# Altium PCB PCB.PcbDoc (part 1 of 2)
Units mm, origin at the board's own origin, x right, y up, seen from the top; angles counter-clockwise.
Board outline 73.15 x 70.89 mm, 4 copper layers (Top Layer, Int1 (GND), Int2 (PWR), Bottom Layer), stack 1.369 mm thick; 101 components, 61 nets, 289 pads, 185 vias.
Unrouted connection lines stored in the file: 20.
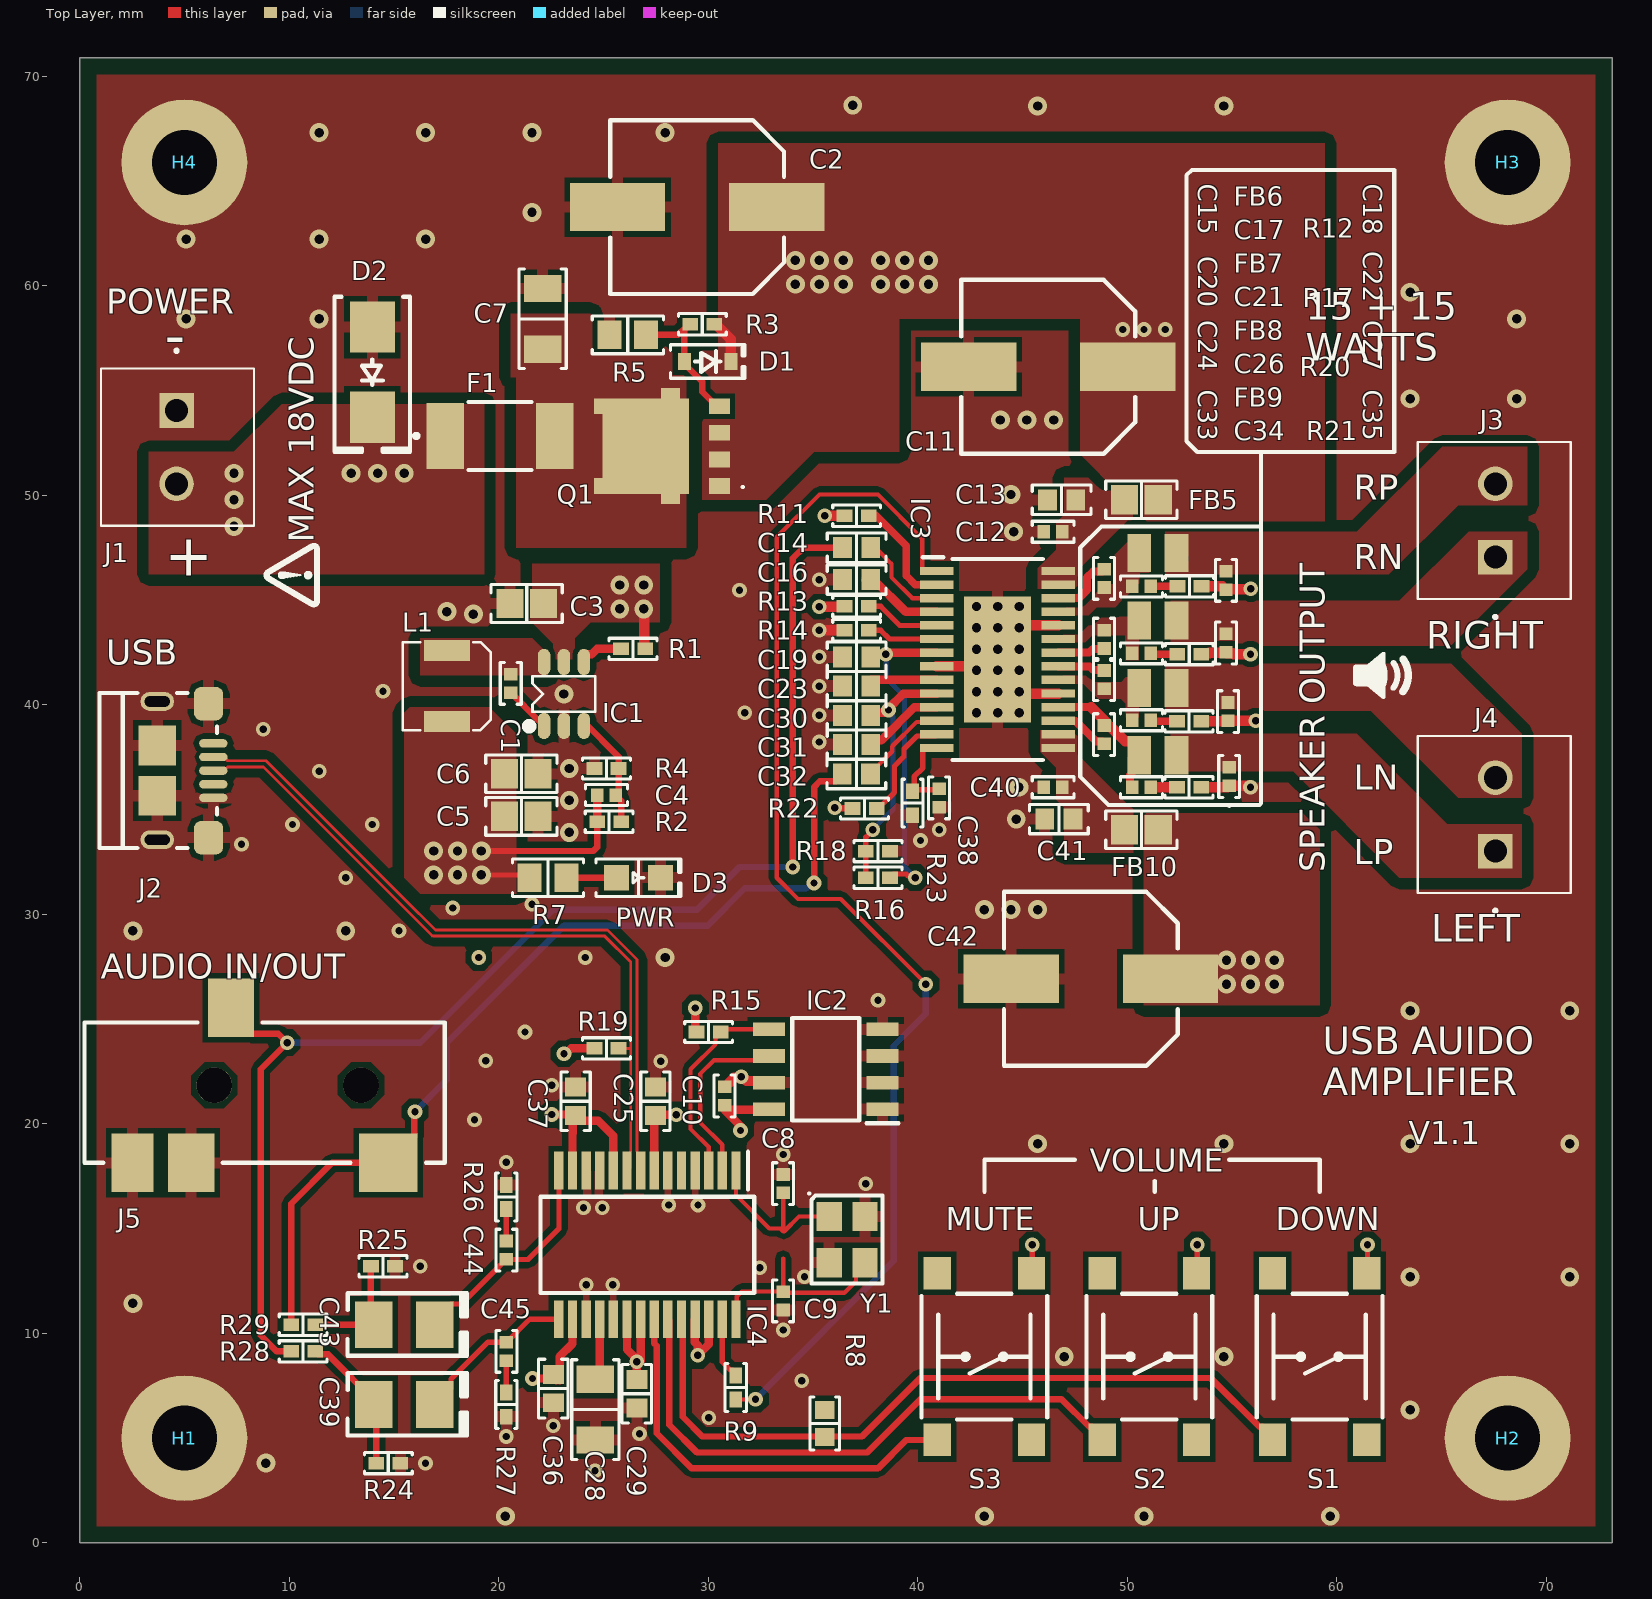
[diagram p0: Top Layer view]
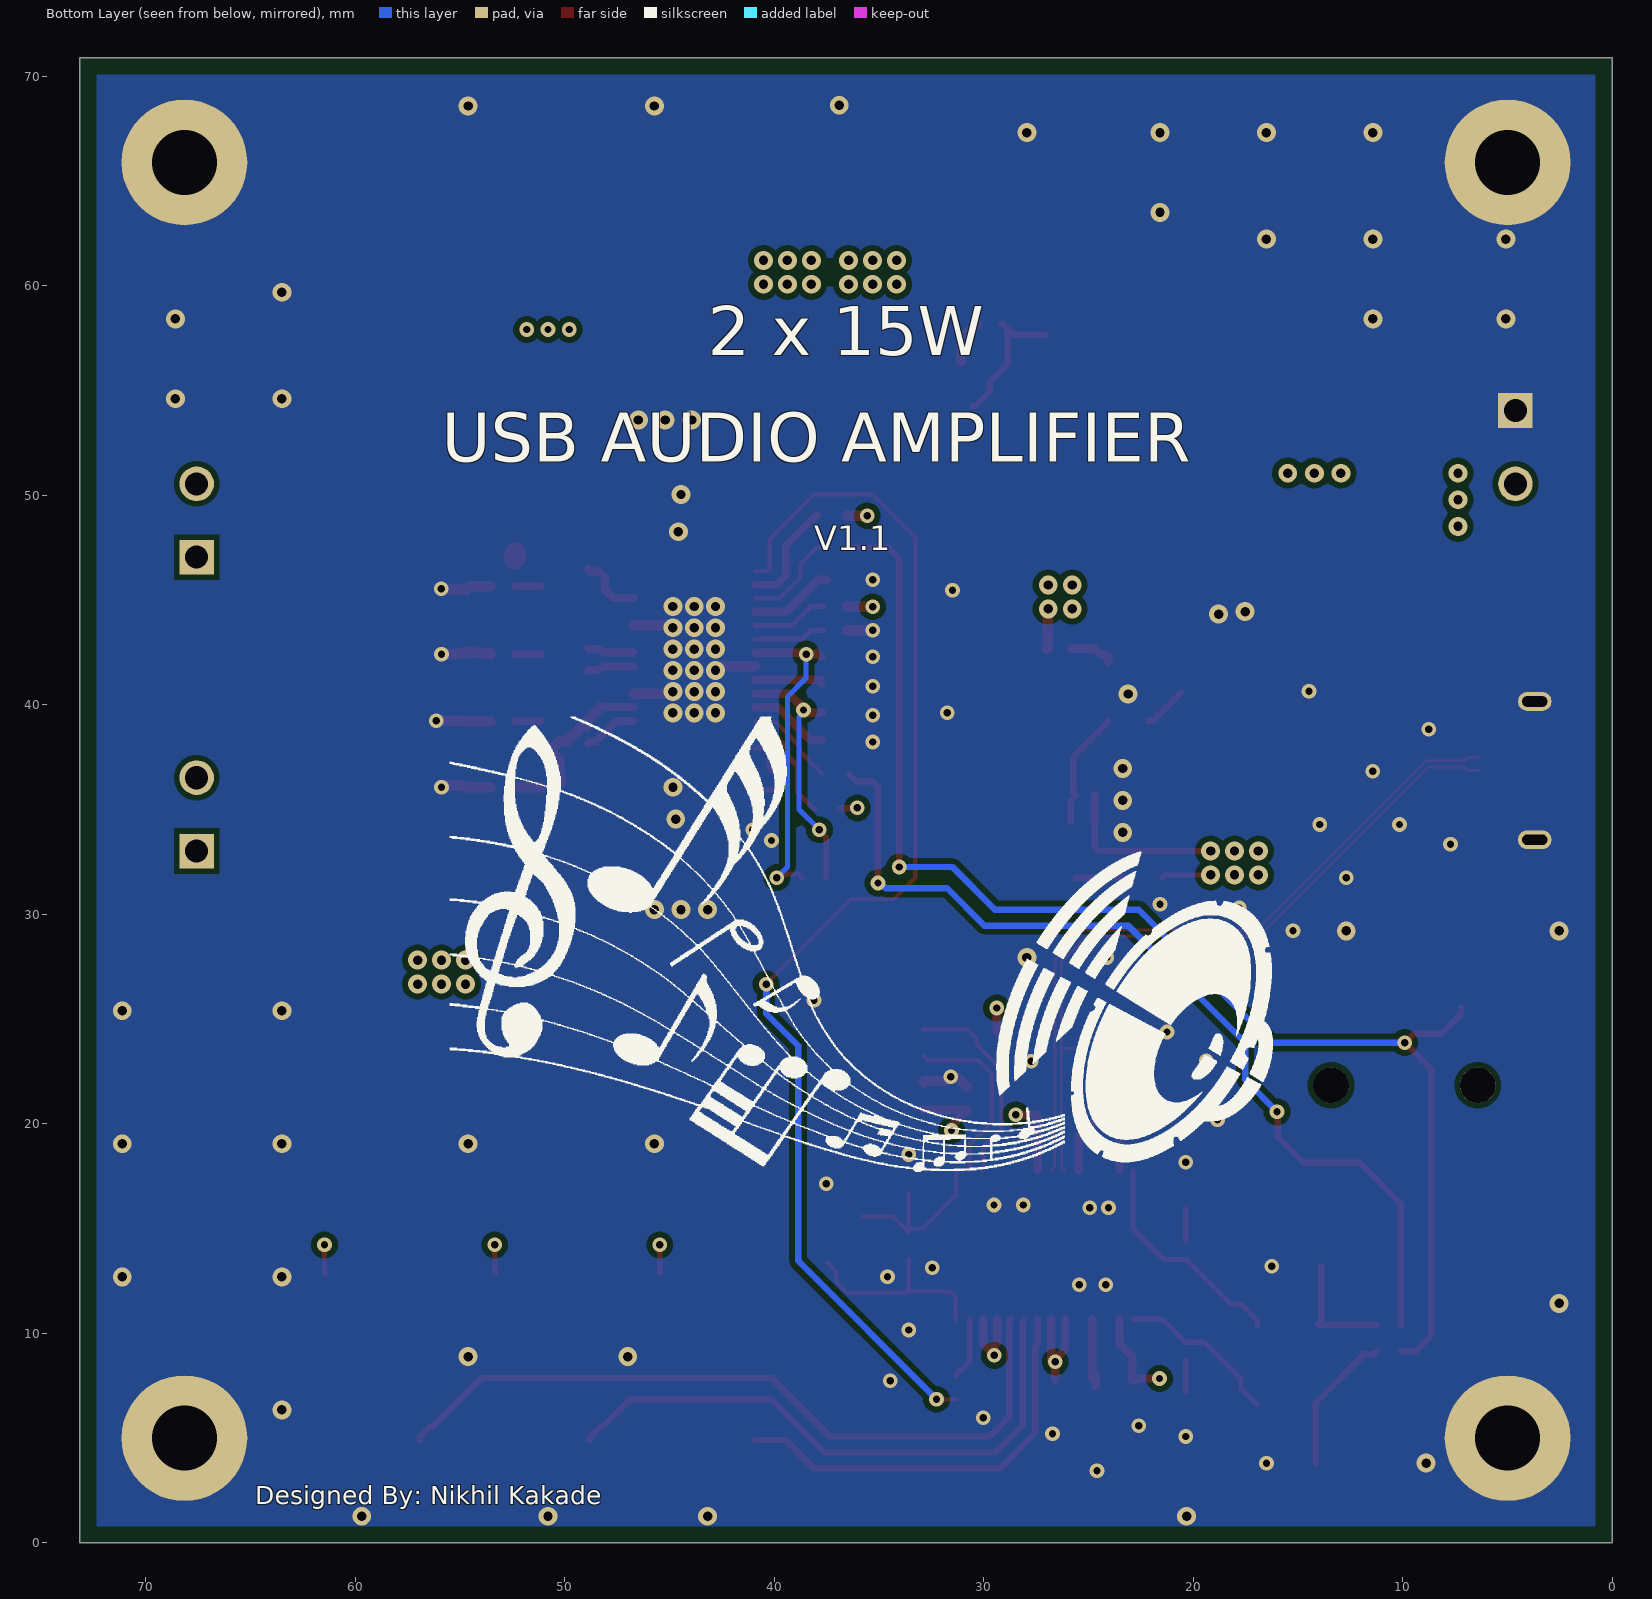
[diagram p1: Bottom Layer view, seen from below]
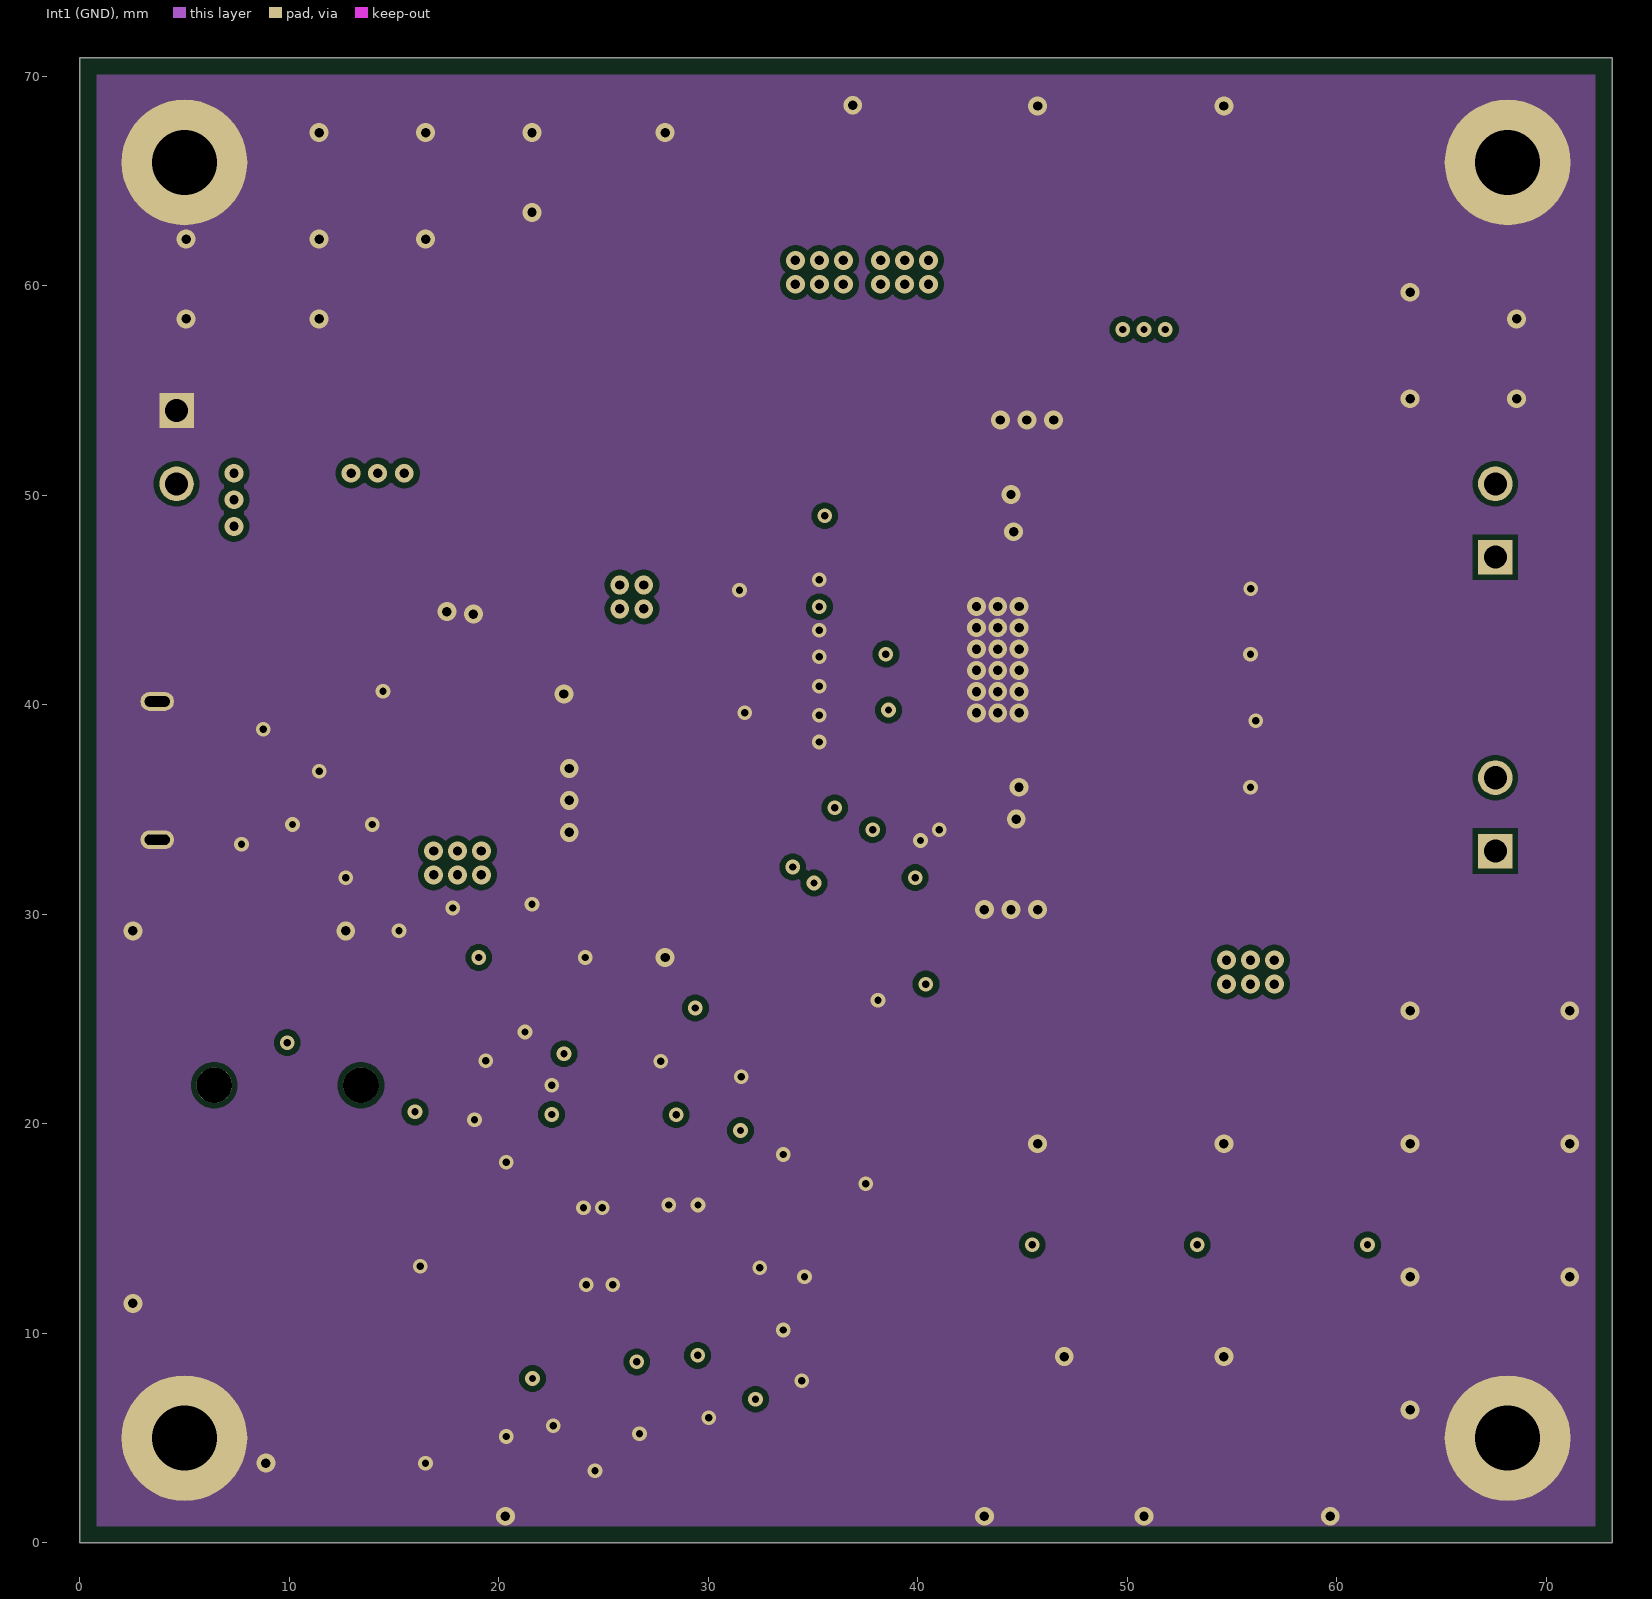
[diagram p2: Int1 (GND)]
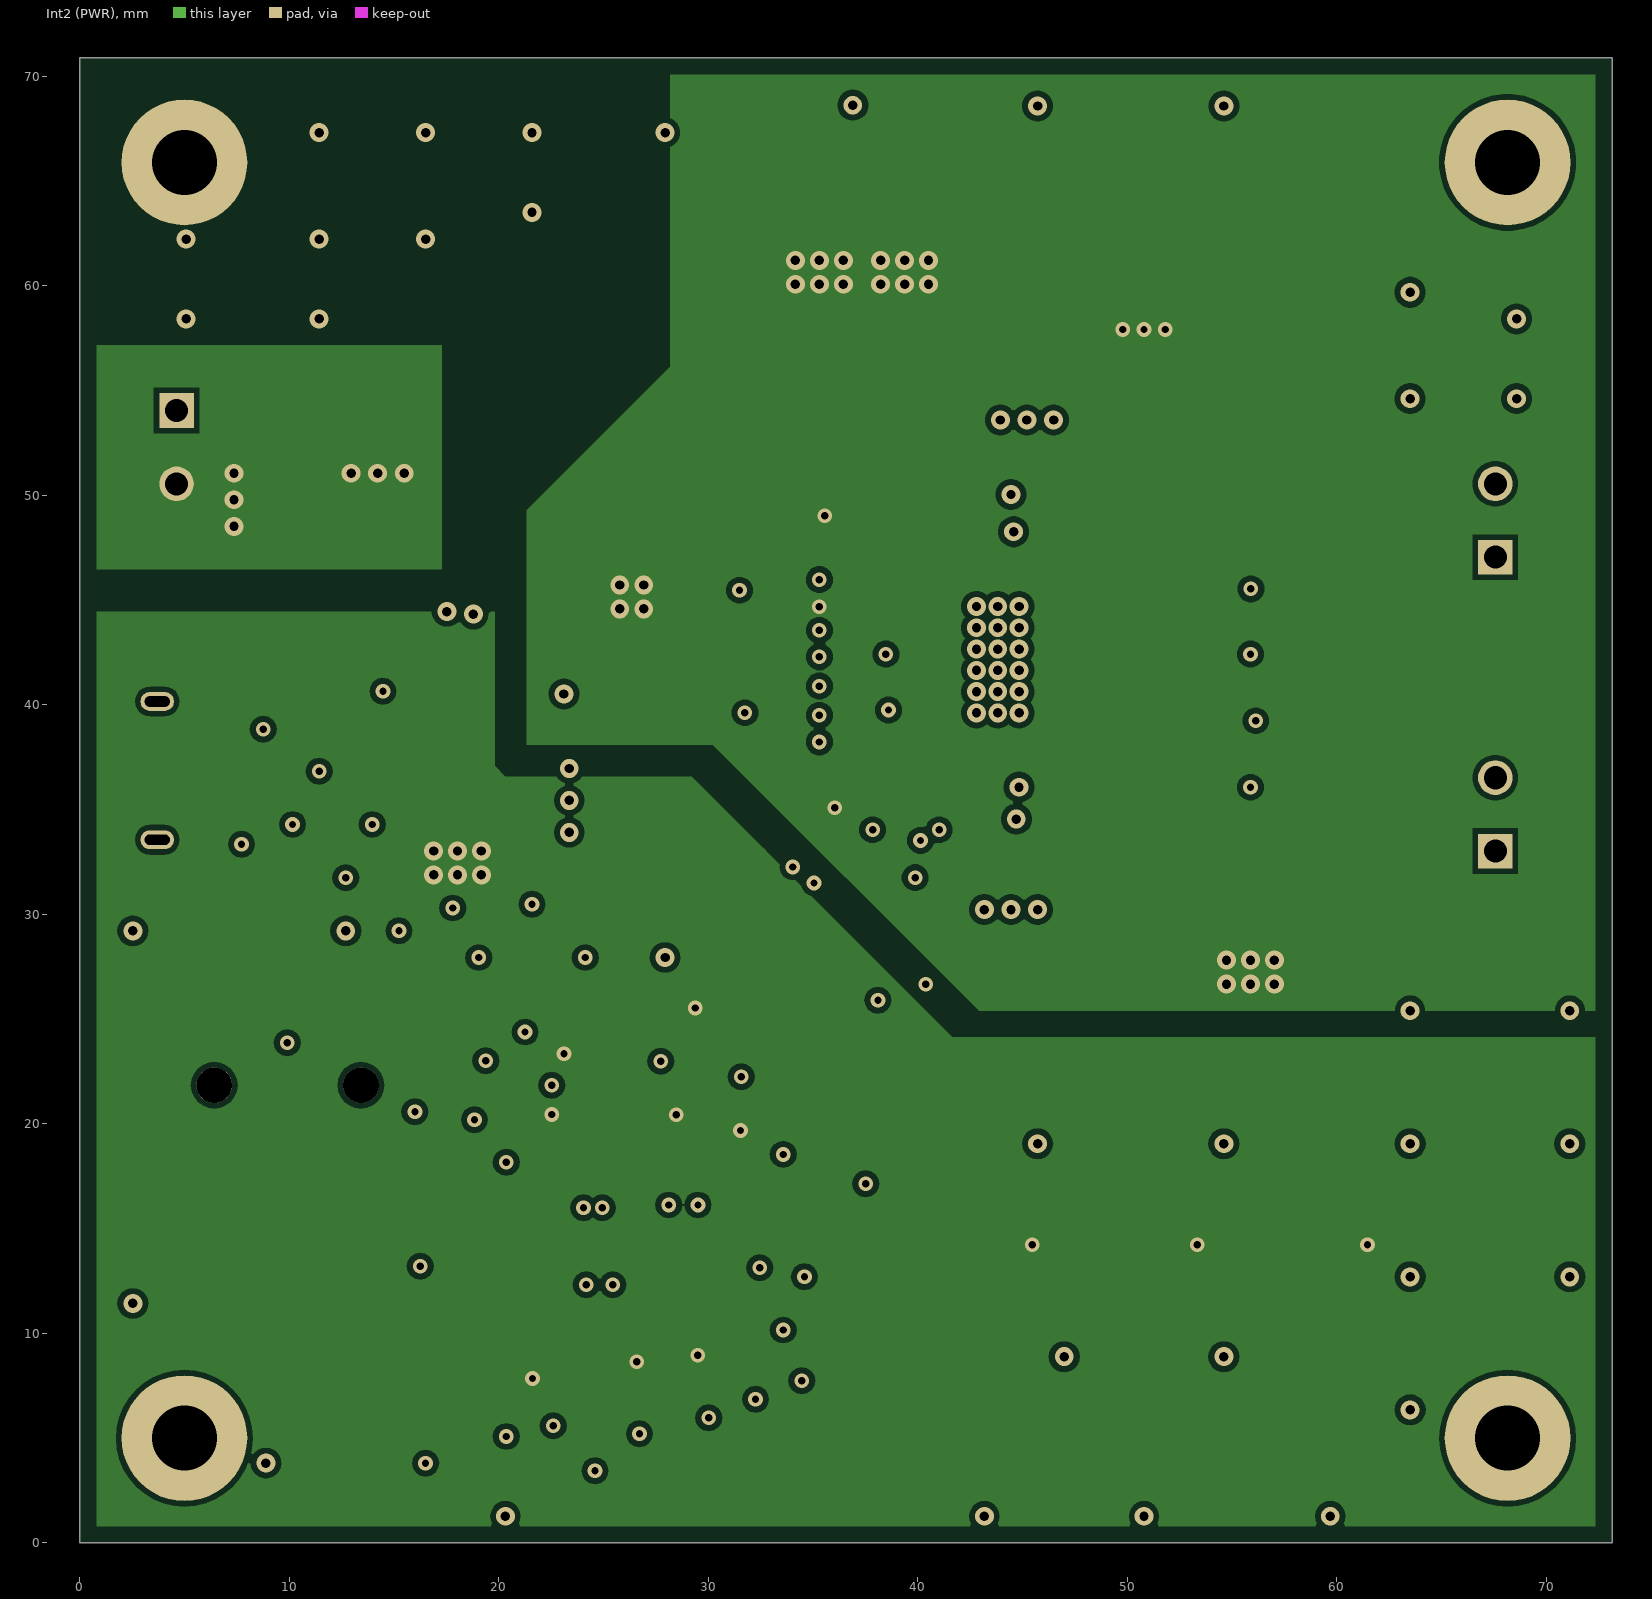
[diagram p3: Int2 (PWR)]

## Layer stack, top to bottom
Top Solder: solder mask 0.0254, SM-001, Dk 4
Top Layer: signal copper 0.035
Dielectric 1: prepreg 0.1295, PP-017, Dk 4.3
Dielectric 2: prepreg 0.1295, PP-017, Dk 4.3
Int1 (GND): signal copper 0.035
Dielectric 3: core 0.7112, Core-039, Dk 4.8
Int2 (PWR): signal copper 0.035
Dielectric 4: prepreg 0.1295, PP-017, Dk 4.3
Dielectric 5: prepreg 0.1295, PP-017, Dk 4.3
Bottom Layer: signal copper 0.035
Bottom Solder: solder mask 0.0254, SM-001, Dk 4

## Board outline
0,0 73.152,0 73.152,70.888 0,70.888

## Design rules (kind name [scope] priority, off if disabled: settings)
AssemblyTestpoint [All] p1: testpointundercomponent=TRUE minsize=1.016 maxsize=2.54 preferedsize=1.524 minholesize=0 maxholesize=1.016 preferedholesize=0.813 testpointgrid=0.025 usegrid=TRUE gridoriginx=-22.86 gridoriginy=-3.429 gridtolerance=0 allowsidetop=TRUE allowsidebottom=TRUE
BoardOutlineClearance [All] p1: gap=0.8 ignorepadtopadclearanceinfootprint=FALSE except(0.4: Text-OutlineEdge)
Clearance "DIFF PAIR TO PAIR_VIA" [InDifferentialPairClass('SS_DIFF85') AND IsVia OR InDifferentialPairClass('HS_DIFF90') AND Isvia vs InDifferentialPairClass('SS_DIFF85') AND IsVia OR InDifferentialPairClass('HS_DIFF90') AND IsVia] p1: gap=0.254 ignorepadtopadclearanceinfootprint=TRUE
Clearance "SuperSpeed Clearance" [InNetClass('SS_DIFF85') OR InNetClass('HS_DIFF90') vs InNet('GND') OR InNet('+1V2') OR InNet('+3V3') OR InNet('+5V') OR InNet('+1V05')] p2: gap=0.178 ignorepadtopadclearanceinfootprint=TRUE except(0.127: Arc-SMDPad Track-SMDPad; 0.152: Arc-Arc Arc-Track Arc-Via Track-Track Track-Via SMDPad-Via; 0.381: Arc-Fill Arc-Poly Arc-Region Track-Fill Track-Poly Track-Region Via-Fill Via-Poly Via-Region; 0.4: Fill-Fill Fill-Poly Fill-Region Poly-Poly Poly-Region Region-Region)
Clearance "Pair to Pair SS Clearance" [InNetClass('SS_DIFF85') vs InAnyNet and IsDifferentialPair] p3: gap=0.5 ignorepadtopadclearanceinfootprint=TRUE
Clearance "Clearance_PWR _plane" [InNamedPolygon('NONET_L03_P031')  OR InNamedPolygon('+1V05_L04_P023')] p4: gap=0.203 ignorepadtopadclearanceinfootprint=TRUE except(0.5: Fill-Fill Fill-Poly Fill-Region Poly-Poly Poly-Region Region-Region)
Clearance [All] p5: gap=0.254 ignorepadtopadclearanceinfootprint=TRUE except(0: Arc-Hole Track-Hole SMDPad-Hole THPad-Hole Via-Hole Fill-Hole Poly-Hole Region-Hole Text-Hole; 0.102: Arc-SMDPad Arc-Via Track-SMDPad Track-Via; 0.127: Arc-Arc Arc-Track Arc-THPad Track-Track Track-THPad SMDPad-SMDPad SMDPad-THPad SMDPad-Via Via-Via; 0.279: Via-Fill Via-Poly Via-Region; 0.5: Fill-Fill Fill-Poly Fill-Region Poly-Poly Poly-Region Region-Region)
DiffPairsRouting "SuperSpeed DiffPairs_85" [InDifferentialPairClass('SS_DIFF85')] p1: maxlimit=0.152 minlimit=0.152 mostfreqgap=0.152 toplayer_minwidth=0.159 toplayer_maxwidth=0.159 toplayer_prefwidth=0.159 midlayer1_minwidth=0.159 midlayer1_maxwidth=0.159 midlayer1_prefwidth=0.159 midlayer2_minwidth=0.159 midlayer2_maxwidth=0.159 midlayer2_prefwidth=0.159 bottomlayer_minwidth=0.159 bottomlayer_maxwidth=0.159 bottomlayer_prefwidth=0.159 maxuncoupledlength=12.7
DiffPairsRouting "HighSpeed DiffPairs_90" [InDifferentialPairClass('HS_DIFF90')] p2: maxlimit=0.152 minlimit=0.152 mostfreqgap=0.152 toplayer_minwidth=0.141 toplayer_maxwidth=0.141 toplayer_prefwidth=0.141 midlayer1_minwidth=0.141 midlayer1_maxwidth=0.141 midlayer1_prefwidth=0.141 midlayer2_minwidth=0.141 midlayer2_maxwidth=0.141 midlayer2_prefwidth=0.141 bottomlayer_minwidth=0.141 bottomlayer_maxwidth=0.141 bottomlayer_prefwidth=0.141 maxuncoupledlength=12.7
FabricationTestpoint [All] p1: side=3 testpointundercomponent=TRUE minsize=1.016 maxsize=2.54 preferedsize=1.524 minholesize=0 maxholesize=1.016 preferedholesize=0.813 testpointgrid=0.025 allowsidetop=TRUE allowsidebottom=TRUE usegrid=TRUE gridoriginx=-22.86 gridoriginy=-3.429 gridtolerance=0
HoleSize [All] p1: absolutevalues=TRUE maxlimit=6 minlimit=0.2 maxpercent=80.000 minpercent=20.000
MatchedLengths "DIFF90 HS" [InDifferentialPairClass('HS_DIFF90')] p1: tolerance=0.203 checknetsindiffpair=TRUE checkdiffpairvsdiffpair=FALSE checkxsignals=FALSE checkothers=FALSE
MatchedLengths "DIFF85 SS" [InDifferentialPairClass('SS_DIFF85')] p2: tolerance=0.051 checknetsindiffpair=TRUE checkdiffpairvsdiffpair=FALSE checkxsignals=FALSE checkothers=FALSE
MinimumSolderMaskSliver [All] p1: minsoldermaskwidth=0.09
PlaneClearance [All] p1: clearance=0.762
PolygonConnect PolygonConnect_1 [All vs IsNamedPolygon('GND_L01_P080')] p1: thpad.connectstyle=Direct thpad.reliefconductorwidth=0.254 thpad.reliefentries=4 thpad.polygonreliefangle="90 Angle" thpad.airgapwidth=0.254 smdpad.connectstyle=Relief smdpad.reliefconductorwidth=0.55 smdpad.reliefentries=4 smdpad.polygonreliefangle="90 Angle" smdpad.airgapwidth=0.254 via.connectstyle=Direct via.reliefconductorwidth=0.254 via.reliefentries=4 via.polygonreliefangle="90 Angle" via.airgapwidth=0.254
PolygonConnect [All] p2: connectstyle=Direct reliefconductorwidth=0.254 reliefentries=4 polygonreliefangle="90 Angle" airgapwidth=0.254
RoomDefinition Power [InComponentClass('Power')] p1: confinementstyle=ConfineIn formatcopy=TRUE lockcomponents=FALSE outline 0,-7.112 9.144,-7.112 9.144,2.642 0,2.642
RoomDefinition Audio [InComponentClass('Audio')] p2: confinementstyle=ConfineIn formatcopy=TRUE lockcomponents=FALSE outline 178.943,155.067
RoutingCorners Differential_Corners [(InDifferentialPairClass('HS_DIFF90'))] p1: cornerstyle=Round minsetback=5 maxsetback=5
RoutingCorners [All] p2: cornerstyle=45-Degree minsetback=2.54 maxsetback=2.54
RoutingVias "Diff Pair Via" [InDifferentialPairClass('All Differential Pairs')] p1: holewidth=0.203 width=0.406 viastyle="Through Hole" minholewidth=0.203 minwidth=0.406 maxholewidth=0.203 maxwidth=0.406
RoutingVias [All] p2: holewidth=0.35 width=0.7 viastyle="Through Hole" minholewidth=0.2 minwidth=0.35 maxholewidth=0.711 maxwidth=1.27
SolderMaskExpansion [All] p1: expansion=0.102 istentingtop=FALSE
Width [All] p1: maxlimit=3 minlimit=0.102 preferedwidth=0.127
23 further rules are at their usual default settings.

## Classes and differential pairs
differential pair class HS_DIFF90: AUD_D D1 D2 D3 DAC_D DOWN_D1 DOWN_D2 HSD3 HUB_D UP_D
net class HS_DIFF90: AUD_D_N AUD_D_P DB_N DB_P
component class Power: C1 C2 C3 C4 C5 C6 C7 D1 D2 D3 F1 H1 H2 H3 H4 IC1 J1 J2 L1 Q1 R1 R2 R3 R4 R5 R7
component class Audio: C8 C9 C10 C11 C12 C13 C14 C15 C16 C17 C18 C19 C20 C21 C22 C23 C24 C25 C26 C27 C28 C29 C30 C31 C32 C33 C34 C35 C36 C37 C38 C39 C40 C41 C42 C43 C44 C45 FB5 FB6 FB7 FB8 FB9 FB10 IC2 IC3 IC4 J3 J4 J5 R8 R9 R11 R12 R13 R14 R15 R16 R17 R18 R19 R20 R21 R22 R23 R24 R25 R26 R27 R28 R29 S1 S2 S3 Y1
differential pair AUD_D: +AUD_D_P -AUD_D_N

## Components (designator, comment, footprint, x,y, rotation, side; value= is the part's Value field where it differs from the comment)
C1 "0.1µF" "CAP 0402_1005" 20.574,41.025 r90 top
C2 "100 µF" "CAP ALSMD 8.3MM H10.5MM" 29.474,63.754 r180 top
C3 "22 µF" "CAP 0805_2012" 21.336,44.835 r0 top
C4 "220 pF" "CAP 0402_1005" 25.146,35.691 r180 top
C5 "22 µF" "CAP 0805_2012" 21.082,34.675 r180 top
C6 "22 µF" "CAP 0805_2012" 21.082,36.707 r180 top
C7 "10 µF" "CAP 1206_3216 - 0.8MM" 22.098,58.42 r270 top
C8 "10pF" "CAP 0402_1005" 33.576,17.145 r90 top
C9 "10pF" "CAP 0402_1005" 33.576,11.557 r270 top
C10 "0.1µF" "CAP 0402_1005" 30.782,21.336 r270 top
C11 "220 µF" "CAP ALSMD 8.3MM H10.5MM" 46.228,56.134 r180 top
C12 "1000pF" "CAP 0402_1005" 46.463,48.26 r0 top
C13 "1 µF" "CAP 0603_1608" 46.863,49.784 r0 top
C14 "1 µF" "CAP 0603_1608" 37.084,47.498 r0 top
C15 "0.22µF" "CAP 0402_1005" 48.894,46.038 r270 top
C16 "1 µF" "CAP 0603_1608" 37.084,45.974 r0 top
C17 "330pF" "CAP 0402_1005" 50.684,45.654 r0 top
C18 "1000pF" "CAP 0402_1005" 54.712,45.94 r90 top
C19 "1 µF" "CAP 0603_1608" 37.084,42.291 r0 top
C20 "0.22µF" "CAP 0402_1005" 48.894,43.129 r90 top
C21 "330pF" "CAP 0402_1005" 50.684,42.459 r0 top
C22 "1000pF" "CAP 0402_1005" 54.712,42.954 r90 top
C23 "1 µF" "CAP 0603_1608" 37.084,40.894 r180 top
C24 "0.22µF" "CAP 0402_1005" 48.894,41.199 r270 top
C25 "1 µF" "CAP 0603_1608" 27.48,21.082 r270 top
C26 "330pF" "CAP 0402_1005" 50.684,39.263 r0 top
C27 "1000pF" "CAP 0402_1005" 54.807,39.671 r90 top
C28 "10 µF" "CAP 1206_3216 - 0.8MM" 24.611,6.365 r90 top
C29 "1 µF" "CAP 0603_1608" 26.592,7.118 r90 top
C30 "1 µF" "CAP 0603_1608" 37.084,39.497 r0 top
C31 "1 µF" "CAP 0603_1608" 37.084,38.1 r0 top
C32 "1 µF" "CAP 0603_1608" 37.072,36.694 r0 top
C33 "0.22µF" "CAP 0402_1005" 48.894,38.574 r90 top
C34 "330pF" "CAP 0402_1005" 50.684,36.068 r0 top
C35 "1000pF" "CAP 0402_1005" 54.864,36.576 r90 top
C36 "1 µF" "CAP 0603_1608" 22.606,7.366 r90 top
C37 "1 µF" "CAP 0603_1608" 23.67,21.082 r270 top
C38 "DNP" "CAP 0402_1005" 41.021,35.56 r90 top
C39 "100µF" "CAP POL 1411_3528" 15.494,6.604 r180 top
C40 "1000pF" "CAP 0402_1005" 46.463,36.068 r0 top
C41 "1 µF" "CAP 0603_1608" 46.736,34.544 r0 top
C42 "220 µF" "CAP ALSMD 8.3MM H10.5MM" 48.26,26.924 r180 top
C43 "100µF" "CAP POL 1411_3528" 15.494,10.414 r180 top
C44 "0.022µF" "CAP 0402_1005" 20.368,13.97 r270 top
C45 "0.022µF" "CAP 0402_1005" 20.368,9.144 r90 top
D1 "BZX384-C18,115" SOD323 29.972,56.388 r0 top
D2 "SZ1SMB30CAT3G" "DO214AA SMB" 13.97,55.88 r270 top
D3 "Yellow" "LED 0805_2012 YELLOW" 26.67,31.75 r0 top
F1 "2A" 1812L010DR 20.066,52.832 r0 top
FB5 "180 Ohms @ 100MHz" "FER 0805_2012" 50.673,49.784 r0 top
FB6 "NFZ2MSM601SN10L" BEADC2016X100N 51.46,47.244 r0 top
FB7 "NFZ2MSM601SN10L" BEADC2016X100N 51.46,44.027 r0 top
FB8 "NFZ2MSM601SN10L" BEADC2016X100N 51.46,40.809 r0 top
FB9 "NFZ2MSM601SN10L" BEADC2016X100N 51.46,37.592 r0 top
FB10 "180 Ohms @ 100MHz" "FER 0805_2012" 50.673,34.036 r0 top
H1 "HOLE_4.1mm" M2.0_3.6#1 4.826,5.588 r0 top
H2 "HOLE_4.1mm" M2.0_3.6#2 68.072,5.842 r0 top
H3 "HOLE_4.1mm" M2.0_3.6#3 68.326,65.532 r0 top
H4 "HOLE_4.1mm" M2.0_3.6#4 5.334,65.786 r0 top
IC1 "SY8113IADC" SOT23-6 23.114,40.517 r0 top
IC2 "M24C16-RMN6TP" SOIC127P600X175-8N 35.608,22.606 r180 top
IC3 "MP7758GF" MP7758GF 43.815,42.164 r270 top
IC4 "PCM2704CDBR" SOP65P780X200-28N 27.099,14.224 r270 top
J1 "1985823" 1985823 4.625,54.046 r270 top
J2 "10118193-0001LF" "FCI USB 10118193-0001LF" 3.754,36.86 r90 top
J3 "1985823" 1985823 67.564,47.046 r90 top
J4 "1985823" 1985823 67.564,33.02 r90 top
J5 "SJ-43514-SMT-TR" "CUI SJ-43514-SMT-TR" 9.874,21.86 r90 top
L1 "2.2uH" L4040 17.526,40.894 r270 top
Q1 "NVMFS5A140" NVMFS5A140PLZT1G 27.647,52.344 r90 top
R1 "10 kOhms" "RES 0402_1005" 26.416,42.672 r0 top
R2 "100 kOhms" "RES 0402_1005" 25.273,34.421 r0 top
R3 "10 kOhms" "RES 0402_1005" 29.718,58.166 r0 top
R4 "22.1 kOhms" "RES 0402_1005" 25.146,36.961 r180 top
R5 "1 kOhms" "RES 0805_2012" 26.162,57.658 r0 top
R7 "1 kOhms" "RES 0805_2012" 22.352,31.75 r180 top
R8 "1 MOhms" "RES 0603_1608" 35.56,5.7 r270 top
R9 "0 Ohms" "RES 0402_1005" 31.316,7.417 r90 top
R11 "100 kOhms" "RES 0402_1005" 37.084,49.022 r180 top
R12 "10 Ohms" "RES 0402_1005" 52.97,45.654 r0 top
R13 "100 kOhms" "RES 0402_1005" 37.084,44.704 r180 top
R14 "100 kOhms" "RES 0402_1005" 37.084,43.561 r180 top
R15 "3.3 kOhms" "RES 0402_1005" 30.02,24.384 r0 top
R16 "10 kOhms" "RES 0402_1005" 38.1,31.75 r180 top
R17 "10 Ohms" "RES 0402_1005" 52.959,42.418 r0 top
R18 "10 kOhms" "RES 0402_1005" 38.1,33.02 r0 top
R19 "1.5 kOhms" "RES 0402_1005" 25.146,23.603 r0 top
R20 "10 Ohms" "RES 0402_1005" 52.95,39.21 r180 top
R21 "10 Ohms" "RES 0402_1005" 52.95,36.068 r0 top
R22 "100 kOhms" "RES 0402_1005" 37.465,35.052 r180 top
R23 "0 Ohms" "RES 0402_1005" 39.751,35.306 r90 top
R24 "169 Ohms" "RES 0402_1005" 14.732,3.81 r180 top
R25 "169 Ohms" "RES 0402_1005" 14.478,13.208 r180 top
R26 "16 Ohms" "RES 0402_1005" 20.368,16.51 r270 top
R27 "16 Ohms" "RES 0402_1005" 20.368,6.604 r90 top
R28 "0 Ohms" "RES 0402_1005" 10.668,9.144 r0 top
R29 "0 Ohms" "RES 0402_1005" 10.668,10.414 r0 top
S1 "PTS645SM43SMTR92 LFS" "C&K PTS645" 59.182,8.89 r90 top
S2 "PTS645SM43SMTR92 LFS" "C&K PTS645" 51.054,8.89 r90 top
S3 "PTS645SM43SMTR92 LFS" "C&K PTS645" 43.18,8.89 r90 top
Y1 "12MHz" "ABRACON ABM8G" 36.624,14.478 r270 top

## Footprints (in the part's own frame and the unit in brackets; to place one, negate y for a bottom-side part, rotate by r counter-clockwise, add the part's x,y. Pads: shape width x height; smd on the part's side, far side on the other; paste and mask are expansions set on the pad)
1812L010DR [mm]
  rect 1.78x3.15 smd: 1(-2.615,0) 2(2.615,0)
  silkscreen extent -4.1,-1.62 1.5,1.62, body extent -2.27,-1.63 2.27,1.63, height 0.75
1985823 [mm]
  rect 1.65x1.65 hole 1.1: 1(0,0)
  round 1.65 hole 1.1: 2(3.5,0)
  silkscreen extent -2.9,-3.6 5.5,3.7, body extent -2.12,-3.6 5.5,3.7, height 9.06
"ABRACON ABM8G" [mm] "Crystal, 4-Leads, Body 2.50x3.20mm, Pitch 2.20mm, IPC Medium Density"
  rect 1.4x1.2 smd: 1(-1.1,-0.85) 2(1.1,-0.85) 3(1.1,0.85) 4(-1.1,0.85)
  silkscreen extent -2.25,-1.85 2.1,1.7, body extent -1.61,-1.26 1.61,1.26, height 0.6
BEADC2016X100N [mm]
  rect 1.14x1.82 smd: 1(-0.89,0) 2(0.89,0)
  body extent -1,-0.8 1,0.8, height 1
"C&K PTS645" [mm] "T-Switch, 4-leads, body 6x6mm, C&K PTS645SM43SMTR92 LFS"
  rect 1.55x1.3 smd mask+0.1: 1(-3.975,2.25) 2(3.975,2.25) 3(-3.975,-2.25) 4(3.975,-2.25)
  silkscreen extent -3,-3 3,3, body extent -4.5,-3 4.5,3, height 4.4
"CAP 0402_1005" [mm] "Chip Capacitor, 2-Leads, Body 1.02x0.51mm, IPC Medium Density"
  rect 0.6x0.64 smd: 1(-0.44,0) 2(0.44,0)
  silkscreen extent -1,-0.5 1,0.5, body extent -0.5,-0.26 0.5,0.26, height 0.52
"CAP 0603_1608" [mm] "Chip Capacitor, 2-Leads, Body 1.60x0.80mm, IPC Medium Density"
  rect 0.9x1 smd: 1(-0.675,0) 2(0.675,0)
  silkscreen extent -1.4,-0.7 1.4,0.7, body extent -0.8,-0.41 0.8,0.41, height 0.82
"CAP 0805_2012" [mm] "Chip Capacitor, 2-Leads, Body 2.00x1.20mm, IPC Medium Density"
  rect 1.3x1.4 smd: 1(-0.8,0) 2(0.8,0)
  silkscreen extent -1.7,-0.9 1.7,0.9, body extent -1,-0.64 1,0.64, height 1.26
"CAP 1206_3216 - 0.8MM" [mm] "Chip Capacitor, 2-Leads, Body 3.25x1.60mm, IPC Medium Density"
  rect 1.3x1.8 smd: 1(-1.45,0) 2(1.45,0)
  silkscreen extent -2.37,-1.12 2.37,1.12, body extent -1.6,-0.8 1.6,0.8, height 0.8
"CAP ALSMD 8.3MM H10.5MM" [mm] "Aluminum Electrolytic Capacitor, Body 8.30x8.30x10.50mm, IPC Low Density"
  rect 4.55x2.3 smd: 1(-3.8,0) 2(3.8,0)
  silkscreen extent -4.15,-4.15 4.15,4.15, body extent -4.95,-4.15 4.95,4.15, height 10.5
"CAP POL 1411_3528" [mm] "Molded Capacitor, 2-Leads, Body 3.50x2.80mm, IPC Medium Density"
  rect 1.8x2.23 smd: 1(-1.46,0) 2(1.46,0)
  silkscreen extent -3,-1.5 2.71,1.48, body extent -1.87,-1.45 1.86,1.45, height 2
"CUI SJ-43514-SMT-TR" [mm] "3.50mm (0.141\", 1/8\", Mini Plug) - Headphone Phone Jack Stereo (4 Conductor, TRRS) Connector Solder"
  rect 2.8x2 smd: 1(-3.716,7.348)
  rect 2.8x2.8 smd: 2(-3.716,-4.852)
  rect 2.8x2.2 smd: 3(3.684,2.648) 4(-3.716,4.548)
  round 1.7 hole 1.7 unplated: M(-0.016,3.448) M(-0.016,-3.552)
  silkscreen extent -3.72,-7.55 2.98,9.65, body extent -4.52,-7.55 4.48,9.65, height 5
"DO214AA SMB" [mm] "Molded Diode, 2-Leads, Body 4.31x3.62mm, IPC Medium Density"
  rect 2.45x2.15 smd: 1(-2.15,0) 2(2.15,0)
  silkscreen extent -3.6,-1.8 3.8,1.8, body extent -2.6,-1.8 2.6,1.8, height 2.4
"FCI USB 10118193-0001LF" [mm] "USB 2.0 Type B Micro"
  oval 0.4x1.35 smd: 1(1.3,-2.625) 2(0.65,-2.625) 3(0,-2.625) 4(-0.65,-2.625) 5(-1.3,-2.625)
  oval 0.9x1.6 hole 0.5 slot 1.2 at 90 deg: S(-3.3,0.05) S(3.3,0.05)
  rrect50% 1.6x1.4 smd: S(-3.2,-2.4) S(3.2,-2.4)
  rect 1.9x1.8 smd: S(-1.2,0.05) S(1.2,0.05)
  silkscreen extent -3.7,-2.8 3.7,2.8, body extent -3.93,-2.9 3.93,2.76, height 2.78
"FER 0805_2012" [mm] "Chip Ferrite, 2-Leads, Body 2.00x1.20mm, IPC Medium Density"
  rect 1.3x1.4 smd: 1(-0.8,0) 2(0.8,0)
  silkscreen extent -1.7,-0.9 1.7,0.9, body extent -1,-0.64 1,0.64, height 1.26
L4040 [mm]
  rect 1x2.2 smd: 1(-1.7,0) 2(1.7,0)
  silkscreen extent -2.1,-2.1 2.1,2.1, body extent -2,-2 2,2, height 1.8
"LED 0805_2012 YELLOW" [mm] "Chip Diode, 2-Leads, Body 2.00x1.25mm, IPC Medium Density"
  rect 1.2x1.2 smd: 1(-1.05,0) 2(1.05,0)
  silkscreen extent -2.03,-0.9 2.03,0.9, body extent -1,-0.62 1,0.63, height 0.9
M2.0_3.6#1 [mm]
  round 6 hole 3.1: 1(0.174,-0.588)
M2.0_3.6#2 [mm]
  round 6 hole 3.1: 1(0.08,-0.842)
M2.0_3.6#3 [mm]
  round 6 hole 3.1: 1(-0.174,0.356)
M2.0_3.6#4 [mm]
  round 6 hole 3.1: 1(-0.334,0.102)
MP7758GF [mm] "TSSOP-28"
  rect 0.4x1.6 smd: 1(-4.225,-2.9) 2(-3.575,-2.9) 3(-2.925,-2.9) 4(-2.275,-2.9) 5(-1.625,-2.9) 6(-0.975,-2.9) 7(-0.325,-2.9) 8(0.325,-2.9) 9(0.975,-2.9) 10(1.625,-2.9) 11(2.275,-2.9) 12(2.925,-2.9) 13(3.575,-2.9) 14(4.225,-2.9) 15(4.225,2.9) 16(3.575,2.9) 17(2.925,2.9) 18(2.275,2.9) 19(1.625,2.9) 20(0.975,2.9) 21(0.325,2.9) 22(-0.325,2.9) 23(-0.975,2.9) 24(-1.625,2.9) 25(-2.275,2.9) 26(-2.925,2.9) 27(-3.575,2.9) 28(-4.225,2.9)
  rect 6x3.2 smd: EPAD(0,0)
  silkscreen extent -4.87,-3.57 4.8,2.15, body extent -4.85,-3.2 4.85,3.2, height 1.13
NVMFS5A140PLZT1G [mm]
  rect 0.75x1 smd: 1(-1.905,-2.89) 2(-0.635,-2.89) 3(0.635,-2.89) 4(1.905,-2.89)
  rect 4.56x4.105 smd: 5(0,0.628)
  rect 0.75x0.425 smd: 6(1.905,2.89) 7(-1.905,2.89)
  rect 0.495x0.905 smd: 8(2.52,-0.547) 9(-2.52,-0.547)
  silkscreen extent -2,-4.05 -1.9,-3.95, body extent -2.72,-3.31 2.72,3.06, height 1.2
"RES 0402_1005" [mm] "Chip Resistor, 2-Leads, Body 1.0x0.5mm, IPC Medium Density"
  rect 0.75x0.6 smd: 1(-0.575,0) 2(0.575,0)
  silkscreen extent -1.14,-0.51 1.14,0.51, body extent -0.5,-0.25 0.5,0.25, height 0.35
"RES 0603_1608" [mm] "Chip Resistor, 2-Leads, Body 1.60x0.80mm, IPC Medium Density"
  rect 0.85x0.95 smd: 1(-0.65,0) 2(0.65,0)
  silkscreen extent -1.27,-0.7 1.27,0.7, body extent -0.8,-0.4 0.8,0.4, height 0.45
"RES 0805_2012" [mm] "Chip Resistor, 2-Leads, Body 2.00x1.25mm, IPC Medium Density"
  rect 1.15x1.35 smd: 1(-0.875,0) 2(0.875,0)
  silkscreen extent -1.7,-0.9 1.7,0.9, body extent -1,-0.62 1,0.63, height 0.6
SOD323 [mm] "SOD, 2-Leads, Body 1.25x2.50mm, IPC Medium Density"
  rect 0.625x0.83 smd: 1(-1.112,0) 2(1.112,0)
  silkscreen extent -1.78,-0.8 1.78,0.8, body extent -1.36,-0.62 1.36,0.62, height 1.05
SOIC127P600X175-8N [mm]
  rect 1.525x0.65 smd: 1(-2.712,1.905) 2(-2.712,0.635) 3(-2.712,-0.635) 4(-2.712,-1.905) 5(2.712,-1.905) 6(2.712,-0.635) 7(2.712,0.635) 8(2.712,1.905)
  silkscreen extent -3.47,-2.45 1.6,2.58, body extent -3,-2.45 3,2.45, height 1.75
SOP65P780X200-28N [mm]
  rect 1.8x0.45 smd: 1(-3.55,4.225) 2(-3.55,3.575) 3(-3.55,2.925) 4(-3.55,2.275) 5(-3.55,1.625) 6(-3.55,0.975) 7(-3.55,0.325) 8(-3.55,-0.325) 9(-3.55,-0.975) 10(-3.55,-1.625) 11(-3.55,-2.275) 12(-3.55,-2.925) 13(-3.55,-3.575) 14(-3.55,-4.225) 15(3.55,-4.225) 16(3.55,-3.575) 17(3.55,-2.925) 18(3.55,-2.275) 19(3.55,-1.625) 20(3.55,-0.975) 21(3.55,-0.325) 22(3.55,0.325) 23(3.55,0.975) 24(3.55,1.625) 25(3.55,2.275) 26(3.55,2.925) 27(3.55,3.575) 28(3.55,4.225)
  silkscreen extent -4.45,-5.1 2.3,5.1, body extent -3.9,-5.1 3.9,5.1, height 1.9
SOT23-6 [mm]
  oval 0.599x1.25 smd: 1(-0.95,-1.525) 2(0,-1.525) 3(0.95,-1.525) 4(0.95,1.525) 5(0,1.525) 6(-0.95,1.525)
  silkscreen extent -1.81,-1.69 1.5,0.85, body extent -1.46,-1.42 1.46,1.42, height 1.05

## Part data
C1 C10: library part 0402YC104KAT2A, "CAP CER 0.1UF 16V X7R 0402", Device Package="0402 (1005 Metric)", Manufacturer="AVX Corporation", Operating Temperature="-55°C ~ 125°C", Supplier Part Number 1=478-7888-1-ND, Temperature Coefficient=X7R, Tolerance=±10%, Voltage - Rated=16V
C2: library part UWT1H101MNL1GS, "CAP ALUM 100UF 20% 50V SMD", Device Package="Radial, Can - SMD", Lifetime @ Temp.="1000 Hrs @ 105°C", Manufacturer=Nichicon, Operating Temperature="-55°C ~ 105°C", Ripple Current @ High Frequency="210 mA @ 10 kHz", Ripple Current @ Low Frequency="140 mA @ 120 Hz", Supplier Part Number 1=493-2226-1-ND, Tolerance=±20%, Voltage - Rated="50 V"
C3: library part CL21A226MOCLRNC, "CAP CER 22UF 16V X5R 0805", Device Package="0805 (2012 Metric)", Manufacturer="Samsung Electro-Mechanics", Operating Temperature="-55°C ~ 85°C", Supplier Part Number 1=1276-6780-1-ND, Temperature Coefficient=X5R, Tolerance=±20%, Voltage - Rated=25V
C4: library part 885012005063, "CAP CER 220PF 50V C0G/NP0 0402", Device Package="0402 (1005 Metric)", Manufacturer="Würth Elektronik", Operating Temperature="-55°C ~ 125°C", Supplier Part Number 1=732-7477-1-ND, Temperature Coefficient="C0G, NP0", Tolerance=±5%, Voltage - Rated=50V
C5 C6: library part CL21A226MOCLRNC, "CAP CER 22UF 16V X5R 0805", Device Package="0805 (2012 Metric)", Manufacturer="Samsung Electro-Mechanics", Operating Temperature="-55°C ~ 85°C", Supplier Part Number 1=1276-6780-1-ND, Temperature Coefficient=X5R, Tolerance=±20%, Voltage - Rated=16V
C7 C28: library part CL31B106KBHNNNE, "CAP CER 10UF 50V X7R 1206", Device Package="1206 (3216 Metric)", Manufacturer="Samsung Electro-Mechanics", Operating Temperature="-55°C ~ 125°C", Supplier Part Number 1=1276-6767-1-ND, Temperature Coefficient=X7R, Tolerance=±10%, Voltage - Rated=50V
C8 C9: library part GJM1555C1H300FB01D, "CAP CER 10PF 50V C0G/NP0 0402", Capacitance=30pF, Device Package="0402 (1005 Metric)", Manufacturer="Murata Electronics", Operating Temperature="-55°C ~ 125°C", Supplier Part Number 1=490-16379-1-ND, Temperature Coefficient="C0G, NP0", Tolerance=±1%, Voltage - Rated=50V
C11 C42: library part EEE-FK1V221GP, "CAP ALUM 220UF 20% 35V SMD", Device Package="Radial, Can - SMD", Lifetime @ Temp.="5000 Hrs @ 105°C", Manufacturer="Panasonic Electronic Components", Operating Temperature="-55°C ~ 105°C", Ratings=AEC-Q200, Ripple Current @ High Frequency="600 mA @ 100 kHz", Ripple Current @ Low Frequency="450 mA @ 120 Hz", Supplier Part Number 1=PCE4321CT-ND, Tolerance=±20%, Voltage - Rated="35 V"
C12 C18 C22 C27 C35 C40: library part 04025C102KAT4A, "CAP CER 1000PF 50V X7R 0402", Device Package="0402 (1005 Metric)", Manufacturer="AVX Corporation", Operating Temperature="-55°C ~ 125°C", Supplier Part Number 1=478-7631-1-ND, Temperature Coefficient=X7R, Tolerance=±10%, Voltage - Rated=50V
C13 C14 C16 C19 C23 C25 C29 C30 C31 C32 C36 C37 C41: library part C0603C105K4RACAUTO, "CAP CER 0603 1UF 16V X7R 10%"
C15 C20 C24 C33: library part CL05B224KO5NNNC, "CAP CER 0.22UF 16V X7R 0402", Device Package="0402 (1005 Metric)", Manufacturer="Samsung Electro-Mechanics", Operating Temperature="-55°C ~ 125°C", Supplier Part Number 1=1276-1176-1-ND, Temperature Coefficient=X7R, Tolerance=±10%, Voltage - Rated=16V
C17 C21 C26 C34: library part CC0402JRX7R9BB331, "CAP CER 330PF 50V X7R 0402", Device Package="0402 (1005 Metric)", Manufacturer=Yageo, Operating Temperature="-55°C ~ 125°C", Supplier Part Number 1=311-3768-1-ND, Temperature Coefficient=X7R, Tolerance=±5%, Voltage - Rated=50V
C38: library part 04025C102KAT4A, "CAP CER 1000PF 50V X7R 0402", Capacitance=1000pF, Device Package="0402 (1005 Metric)", Manufacturer="AVX Corporation", Operating Temperature="-55°C ~ 125°C", Supplier Part Number 1=478-7631-1-ND, Temperature Coefficient=X7R, Tolerance=±10%, Voltage - Rated=50V
C39 C43: library part F931A107KBA, "CAP TANT 100UF 10% 10V 1411", Device Package="1411 (3528 Metric)", ESR (Equivalent Series Resistance)="1.2Ohm @ 100kHz", Lifetime @ Temp.="2000 Hrs @ 125°C", Manufacturer="AVX Corporation", Manufacturer Size Code=B, Operating Temperature="-55°C ~ 125°C", Supplier Part Number 1=478-8195-1-ND, Tolerance=±10%, Voltage - Rated=10V
C44 C45: library part CL05B223KP5NNNC, "CAP CER 0.022UF 10V X7R 0402", Device Package="0402 (1005 Metric)", Manufacturer="Samsung Electro-Mechanics", Operating Temperature="-55°C ~ 125°C", Supplier Part Number 1=1276-1538-1-ND, Temperature Coefficient=X7R, Tolerance=±10%, Voltage - Rated=10V
D1: library part DDZ9705S-7, "DIODE ZENER 18V 200MW SOD323", Current - Reverse Leakage @ Vr="50 nA @ 13.6 V", Manufacturer="Diodes Incorporated", Operating Temperature="-65°C ~ 150°C", Package / Case="SC-76, SOD-323", Power - Max="200 mW", Supplier Device Package=SOD-323, Supplier Part Number 1=DDZ9705SDICT-ND, Tolerance=±5%, Voltage - Forward (Vf) (Max) @ If="900 mV @ 10 mA", Voltage - Zener (Nom) (Vz)="18 V"
D2: "TVS DIODE 30VWM 48.4VC SMB", Capacitance @ Frequency="290pF @ 1MHz", Current - Peak Pulse (10/1000µs)=12.4A, Manufacturer="Littelfuse Inc.", Operating Temperature="-65°C ~ 150°C (TJ)", Package / Case="DO-214AA, SMB", Power - Peak Pulse=600W, Power Line Protection=No, Supplier Device Package=SMB, Supplier Part Number 1=SZ1SMB30CAT3GCT-ND, Voltage - Breakdown (Min)=33.3V, Voltage - Clamping (Max) @ Ipp=48.4V, Voltage - Reverse Standoff (Typ)=30V
D3: library part VAOL-S8YP4, "LED YELLOW CLEAR 0805 SMD", Current - Test=20mA, Device Package="0805 (2012 Metric)", Lens Color=Colorless, Manufacturer="Visual Communications Company - VCC", Millicandela Rating=92mcd, Supplier Device Package=0805, Supplier Part Number 1=VAOL-S8YP4CT-ND, Voltage - Forward (Vf) (Typ)=2V
F1: library part 1812L150_12, "Resettable Fuse", Manufacturer_Name=LITTELFUSE, Manufacturer_Part_Number=1812L150/12
FB5 FB10: library part 74279220181, "FERRITE BEAD 180 OHM 0805 1LN", Current Rating (Max)=4A, DC Resistance (DCR) (Max)=37mOhm, Device Package="0805 (2012 Metric)", Manufacturer="Würth Elektronik", Operating Temperature="-55°C ~ 125°C", Supplier Part Number 1=732-6123-1-ND
FB6 FB7 FB8 FB9: "Ferrite Beads Multi-Layer 600Ohm 25% 100MHz 2.5A 46mOhm DCR 0806 Automotive T/R", Package=None
H1 H2 H3 H4: library part HOLE_4mm, Manufacturer=NA
IC1: library part MP1584_1
IC2: "Integrated Circuit", Manufacturer_Name=STMicroelectronics, Mouser Part Number=511-M24C16-RMN6TP
IC3: "Amplifier IC 2-Channel (Stereo) Class D 28-TSSOP-EP", Manufacturer="Monolithic Power Systems Inc.", Part Number=MP7758GF-Z
IC4: "Integrated Circuit", Manufacturer_Name="Texas Instruments", Mouser Part Number=595-PCM2704CDBR
J1 J3 J4: "Connector", Manufacturer_Name="Phoenix Contact", Mouser Part Number=651-1985823
J2: "CONN RCPT USB2.0 MICRO B SMD R/A", Current Rating (Amps)="1.8A per Contact", Manufacturer="Amphenol ICC (FCI)", Operating Temperature="-30°C ~ 80°C", Supplier Part Number 1=609-4616-2-ND, Voltage - Rated=100VAC
J5: "CONN JACK 4COND 3.5MM SMD R/A", Manufacturer="CUI Devices", Operating Temperature="-20°C ~ 85°C", Supplier Part Number 1=CP-43514SJCT-ND
L1: library part INDUCTOR_Dup1_1
Q1: library part NVMFS5A140PLZ, "Single P-Channel Power MOSFET, -40 V, -140 A", Current - Continuous Drain (Id) @ 25°C="14A (Ta), 20A (Tc)", Drain to Source Voltage (Vdss)=60V, Drive Voltage (Max Rds On,  Min Rds On)="4.5V, 10V", Input Capacitance (Ciss) (Max) @ Vds="5100pF @ 30V", Manufacturer="Infineon Technologies", Operating Temperature="-55°C ~ 150°C (TJ)", Package / Case=8-PowerVDFN, Part Number=BSZ067N06LS3GATMA1, Power Dissipation (Max)="2.1W (Ta), 69W (Tc)", Supplier Device Package=PG-TSDSON-8, Supplier Part Number 1=BSZ067N06LS3GATMA1CT-ND
R1 R3 R16 R18: library part CRG0402F10K, "RES SMD 10K OHM 1% 1/16W 0402", Device Package="0402 (1005 Metric)", Manufacturer="TE Connectivity Passive Product", Operating Temperature="-55°C ~ 155°C", Power (Watts)="0.063W, 1/16W", Supplier Device Package=0402, Supplier Part Number 1=A121528CT-ND, Temperature Coefficient=±100ppm/°C, Tolerance=±1%
R2: library part RC0402FR-07453KL, "RES 453K OHM 1% 1/16W 0402", Device Package="0402 (1005 Metric)", Manufacturer=Yageo, Operating Temperature="-55°C ~ 155°C", Power (Watts)="0.063W, 1/16W", Resistance="453 kOhms", Supplier Device Package=0402, Supplier Part Number 1=YAG3164CT-ND, Temperature Coefficient=±100ppm/°C, Tolerance=±1%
